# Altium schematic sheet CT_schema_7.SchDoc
size 287 x 160 mm
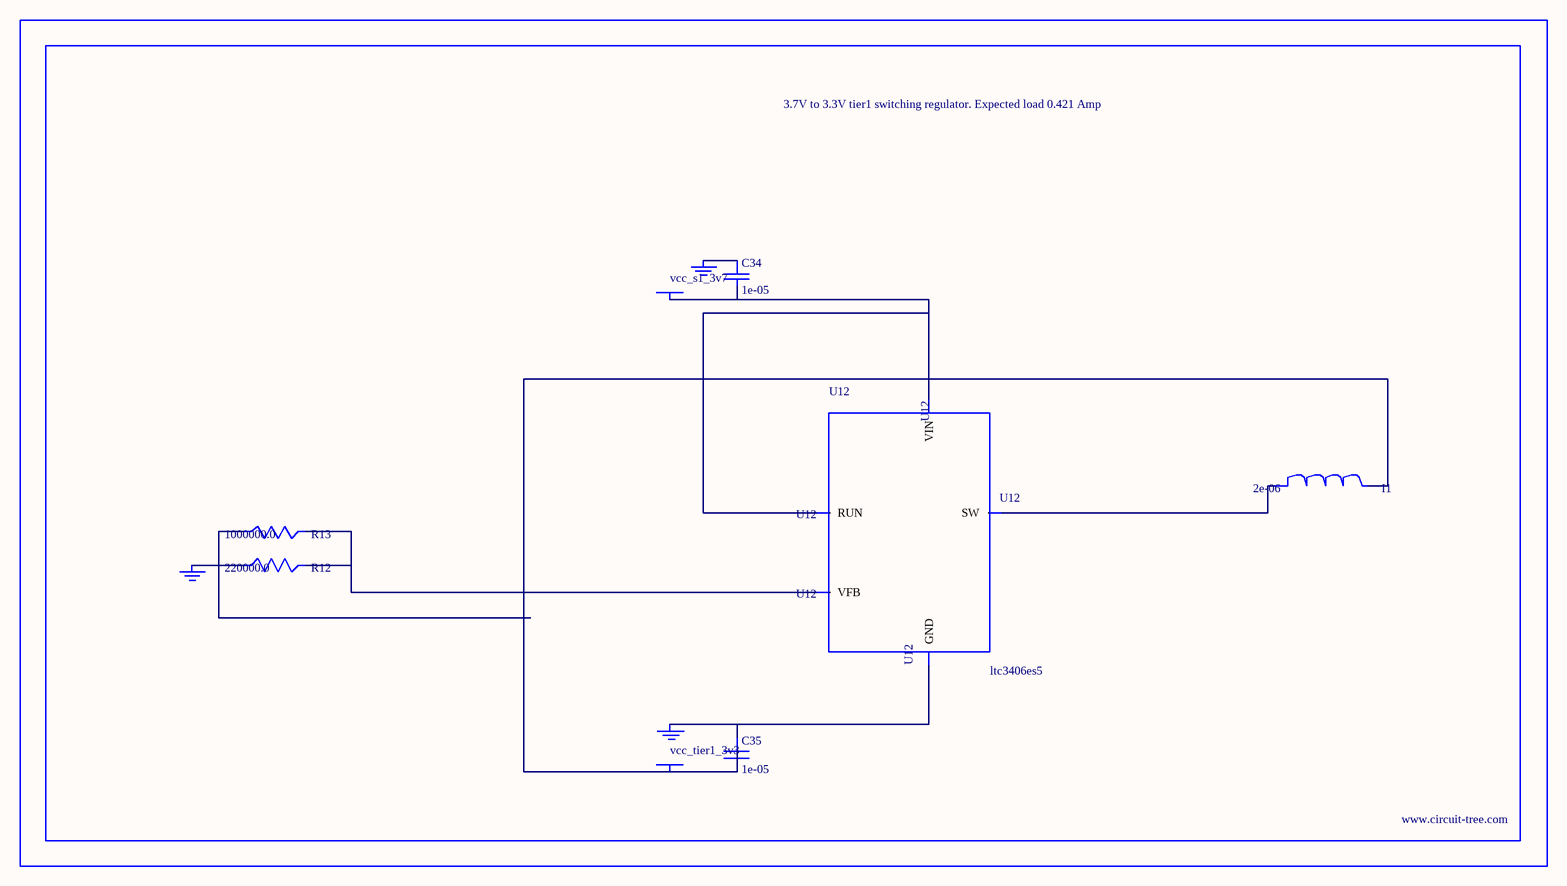
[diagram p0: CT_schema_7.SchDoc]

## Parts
BORDER6  (no value)
C34  1e-05  [C0805]
C35  1e-05  [C0805]
GND_INSTANCE_6_0  (no value)
GND_INSTANCE_6_1  (no value)
GND_INSTANCE_6_2  (no value)
I1  2e-06  [WE-HCI_7030/7040/7050]
POWER_INSTANCE_6_0  vcc_tier1_3v3
POWER_INSTANCE_6_1  vcc_s1_3v7
R12  220000.0  [R0603]
R13  1000000.0  [R0603]
U12  ltc3406es5  [TSOT-23-5]

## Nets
NetC34_1: C34.1 GND_INSTANCE_6_1.0(GND)
NetC34_2: C34.2 POWER_INSTANCE_6_1.0(PWR) U12.1(RUN) U12.4(VIN)
NetC35_1: C35.1 GND_INSTANCE_6_0.0(GND) U12.2(GND)
NetC35_2: C35.2 I1.2 POWER_INSTANCE_6_0.0(PWR) R13.1
NetGND_INSTANCE_6_2_0: GND_INSTANCE_6_2.0(GND) R12.1
NetI1_1: I1.1 U12.3(SW)
NetR12_2: R12.2 R13.2 U12.5(VFB)

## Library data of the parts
BORDER6 = BORDER_PAGE6
C34 C35 = C0805C106K8RACTU
GND_INSTANCE_6_0-GND_INSTANCE_6_2 = GND
I1 = 744314200
POWER_INSTANCE_6_0 POWER_INSTANCE_6_1 = PWR
R12 = RC0603JR-07220KL
R13 = RC0603JR-071ML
